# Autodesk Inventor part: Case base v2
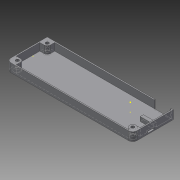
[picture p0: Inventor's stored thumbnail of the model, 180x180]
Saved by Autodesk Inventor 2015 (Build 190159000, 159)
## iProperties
Created: 2018-08
Part Number: Case base v2
Material: Generic
Document SubType Name: Modeling
Designer: Toby
Density: 1 g/cm^3
Appearance: Default
Author: Toby
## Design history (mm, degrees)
sketch "Sketch1"
  geometry: L1 (-84.862, 14.269)-(26.138, 14.269); L2 (26.138, 14.269)-(26.138, -23.731); L3 (26.138, -23.731)-(-84.862, -23.731); L4 (-84.862, -23.731)-(-84.862, 14.269); 1 further point
  constraints: 8 end point, 2 parallel, 1 horizontal, 1 perpendicular
  dimensions: "d0" = 38 distance between parallel lines of L3 L1; "d1" = 111 distance of L1.start L1.end
extrude "Extrusion1" new body sketch "Sketch1" distance "d2" = 1; taper "d3" = 0 deg
sketch "Sketch2"
  geometry: L1 (-84.862, 14.269)-(26.138, 14.269); L2 (26.138, 14.269)-(26.138, -23.731); L3 (26.138, -23.731)-(-84.862, -23.731); L4 (-84.862, -23.731)-(-84.862, 14.269); L5 (-83.862, 13.269)-(25.138, 13.269); L6 (25.138, 13.269)-(25.138, -22.731); L7 (25.138, -22.731)-(-83.862, -22.731); L8 (-83.862, -22.731)-(-83.862, 13.269); 1 further point
  constraints: 16 end point, 4 parallel, 2 horizontal, 2 perpendicular
  dimensions: "d4" = 1 distance between parallel lines of L5 L1; "d5" = 1 distance between parallel lines of L3 L7; "d6" = 1 distance between parallel lines of L4 L8; "d7" = 1 distance between parallel lines of L2 L6
extrude "Extrusion2" join sketch "Sketch2" distance "d8" = 7; taper "d9" = 0 deg
sketch "Sketch3"
  geometry: L1 (25.138, -22.731)-(25.138, 13.269) reference; L2 (25.138, -22.731)-(-83.862, -22.731) reference; C1 r 3 at (21.138, -18.731); 1 further point
  constraints: 1 centre point
  dimensions: "d10" = 6 diameter of C1; "d11" = 4 distance from line of L1 C1.centre; "d12" = 4 distance from line of L2 C1.centre
extrude "Extrusion3" join sketch "Sketch3" distance "d13" = 7; taper "d14" = 0 deg
sketch "Sketch4"
  geometry: C1 r 3 at (0, 0) reference; 2 further points
  constraints: 1 coincident
hole "Hole1" sketch "Sketch4" at (0, 0) diameter "d15" = 3; stored, may be unused: countersink angle "d19" = 90 deg, drill point angle "d21" = 118 deg; dims "d16" = 6, "d17" = 4, "d18" = 2, "d20" = 6
sketch "Sketch5"
  geometry: L1 (4, -4)-(0, -4); L2 (0, -4)-(0, -1.5); L3 (0, -1.5)-(4, -1.5); L4 (4, -1.5)-(4, -4); L5 (4, 32)-(4, -4) reference; L6 (4, 3)-(1.5, 3); L7 (1.5, 3)-(1.5, -1.5); L8 (1.5, -1.5)-(4, -1.5); L9 (4, -1.5)-(4, 3); 2 further points
  constraints: 16 end point, 4 parallel, 2 horizontal, 2 perpendicular, 2 point on line, 1 vertical alignment, 1 other
extrude "Extrusion4" join sketch "Sketch5" distance "d22" = 7; taper "d23" = 0 deg
sketch "Sketch6"
  geometry: L1 (25.138, 13.269)-(25.138, -15.731) reference; L2 (25.138, -0.731)-(13.138, -0.731); L3 (13.138, -0.731)-(13.138, -3.731); L4 (13.138, -3.731)-(25.138, -3.731); L5 (25.138, -3.731)-(25.138, -0.731); L6 (-83.862, 13.269)-(25.138, 13.269) reference; 1 further point
  constraints: 8 end point, 2 parallel, 1 horizontal, 1 perpendicular, 1 point on line
  dimensions: "d24" = 3 distance between parallel lines of L4 L2; "d25" = 14 distance between parallel lines of L6 L2; "d26" = 12 distance between parallel lines of L1 L3
extrude "Extrusion5" join sketch "Sketch6" distance "d27" = 4; taper "d28" = 0 deg
sketch "Sketch7"
  geometry: L1 (111, 0)-(0, 0) reference; L2 (0, -8)-(111, -8) reference; L3 (109, 0)-(94, 0); L4 (94, 0)-(94, -8); L5 (94, -8)-(109, -8); L6 (109, -8)-(109, 0); L7 (110, -1)-(110, -5) reference; 1 further point
  constraints: 8 end point, 2 parallel, 2 point on line, 1 horizontal, 1 perpendicular
  dimensions: "d29" = 1 distance between parallel lines of L7 L6; "d30" = 15 distance between parallel lines of L4 L6
extrude "Extrusion6" cut sketch "Sketch7" distance "d31" = 1; taper "d32" = 0 deg
sketch "Sketch8"
  geometry: 1 further point
sketch "Sketch9"
  geometry: L1 (-5, 20)-(-1, 20) reference; L2 (-1, 8)-(-1, 20) reference; L3 (-2.5, 20)-(-1, 20); L4 (-1, 20)-(-1, 14); L5 (-1, 14)-(-2.5, 14); L6 (-2.5, 14)-(-2.5, 20); 1 further point
  constraints: 8 end point, 2 parallel, 1 horizontal, 1 midpoint, 1 perpendicular, 1 point on line
  dimensions: "d33" = 6 distance of L5.end L3.start; "d34" = 1.5 distance between parallel lines of L2 L6
extrude "Extrusion7" cut sketch "Sketch9" distance "d35" = 1; taper "d36" = 0 deg
sketch "Sketch10"
  geometry: L1 (-84.862, 14.269)-(-89.862, 14.269); L2 (-89.862, 14.269)-(-89.862, -23.731); L3 (-89.862, -23.731)-(-84.862, -23.731); L4 (-84.862, -23.731)-(-84.862, 14.269); L5 (-84.862, -23.731)-(26.138, -23.731) reference; 1 further point
  constraints: 8 end point, 2 parallel, 1 collinear, 1 horizontal, 1 perpendicular
  dimensions: "d37" = 5 distance of L3.end L2.end
extrude "Extrusion8" join sketch "Sketch10" distance "d38" = 1; taper "d39" = 0 deg
sketch "Sketch11"
  geometry: L1 (-83.862, 13.269)-(-83.862, -22.731) reference; L2 (-89.862, 14.269)-(-83.862, 14.269); L3 (-83.862, 14.269)-(-83.862, 8.269); L4 (-83.862, 8.269)-(-89.862, 8.269); L5 (-89.862, 8.269)-(-89.862, 14.269); L6 (-89.862, -23.731)-(-83.862, -23.731); L7 (-83.862, -23.731)-(-83.862, -17.731); L8 (-83.862, -17.731)-(-89.862, -17.731); L9 (-89.862, -17.731)-(-89.862, -23.731); L10 (-89.862, 8.269)-(-88.862, 8.269); L11 (-88.862, 8.269)-(-88.862, -17.731); L12 (-88.862, -17.731)-(-89.862, -17.731); L13 (-89.862, -17.731)-(-89.862, 8.269); 1 further point
  constraints: 24 end point, 6 parallel, 3 horizontal, 3 perpendicular, 3 point on line
  dimensions: "d40" = 6 distance of L2.end L3.end; "d41" = 6 distance of L7.end L6.end; "d42" = 1 distance between parallel lines of L13 L11
extrude "Extrusion9" join sketch "Sketch11" distance "d43" = 7; taper "d44" = 0 deg
sketch "Sketch12"
  geometry: L1 (-84.862, 8.269)-(-83.862, 8.269); L2 (-83.862, 8.269)-(-83.862, -17.731); L3 (-83.862, -17.731)-(-84.862, -17.731); L4 (-84.862, -17.731)-(-84.862, 8.269); L5 (-84.862, -17.731)-(-88.862, -17.731) reference; L6 (-83.862, -22.731)-(-83.862, 13.269) reference; 1 further point
  constraints: 8 end point, 2 collinear, 2 parallel, 1 horizontal, 1 perpendicular
extrude "Extrusion10" cut sketch "Sketch12" distance "d45" = 7; taper "d46" = 0 deg
sketch "Sketch13"
  geometry: L1 (-88.862, 8.269)-(-83.862, 8.269) reference; L2 (-83.862, 8.269)-(-83.862, 13.269) reference; L3 (-83.862, -17.731)-(-88.862, -17.731) reference; 3 further points
  dimensions: "d47" = 3 distance from line of L1 point (-86.862, 11.269); "d48" = 3 distance from line of L2 point (-86.862, 11.269); "d49" = 3 distance from line of L3 point (-86.862, -20.731)
hole "Hole2" sketch "Sketch13" at (-86.862, 11.269), (-86.862, -20.731) diameter "d50" = 3; stored, may be unused: countersink angle "d54" = 90 deg, drill point angle "d56" = 118 deg; dims "d51" = 6, "d52" = 4, "d53" = 2, "d55" = 6
fillet "Fillet1" dims "d57" = 4
fillet "Fillet2" dims "d58" = 2
sketch "Sketch15"
  geometry: L1 (-85.862, -23.731)-(22.138, -23.731) reference; L2 (-89.862, 14.269)-(-83.862, 14.269); L3 (-83.862, 14.269)-(-83.862, -23.731); L4 (-83.862, -23.731)-(-89.862, -23.731); L5 (-89.862, -23.731)-(-89.862, 14.269); L6 (-83.862, 10.269)-(-83.862, 13.269) reference; 1 further point
  constraints: 8 end point, 2 parallel, 1 collinear, 1 horizontal, 1 perpendicular, 1 point on line
extrude "Extrusion11" cut sketch "Sketch15" distance "d59" = 10; taper "d60" = 0 deg
sketch "Sketch16"
  geometry: L1 (-83.862, 14.269)-(-91.862, 14.269); L2 (-91.862, 14.269)-(-91.862, -23.731); L3 (-91.862, -23.731)-(-83.862, -23.731); L4 (-83.862, -23.731)-(-83.862, 14.269); L5 (-83.862, -23.731)-(22.138, -23.731) reference; 1 further point
  constraints: 8 end point, 2 parallel, 1 collinear, 1 horizontal, 1 perpendicular
  dimensions: "d61" = 8 distance between parallel lines of L4 L2
extrude "Extrusion12" join sketch "Sketch16" distance "d62" = 1; taper "d63" = 0 deg
sketch "Sketch17"
  geometry: L1 (22.138, -23.731)-(-91.862, -23.731) reference; L2 (-91.862, 14.269)-(-90.862, 14.269); L3 (-90.862, 14.269)-(-90.862, -23.731); L4 (-90.862, -23.731)-(-91.862, -23.731); L5 (-91.862, -23.731)-(-91.862, 14.269); L6 (-90.862, 14.269)-(-83.862, 14.269); L7 (-83.862, 14.269)-(-83.862, 13.269); L8 (-83.862, 13.269)-(-90.862, 13.269); L9 (-90.862, 13.269)-(-90.862, 14.269); L10 (-83.862, -22.731)-(-90.862, -22.731); L11 (-90.862, -22.731)-(-90.862, -23.731); L12 (-90.862, -23.731)-(-83.862, -23.731); L13 (-83.862, -23.731)-(-83.862, -22.731); 1 further point
  constraints: 24 end point, 6 parallel, 3 horizontal, 3 perpendicular, 1 point on line
  dimensions: "d64" = 1 distance of L3.end L4.end
extrude "Extrusion13" join sketch "Sketch17" distance "d65" = 7; taper "d66" = 0 deg
sketch "Sketch18"
  geometry: 1 further point
sketch "Sketch19"
  geometry: 1 further point
sketch "Sketch20" dims "d67" = 6
  geometry: L1 (-91.862, 14.269)-(-91.862, -23.731) reference; L2 (9.138, 14.269)-(-91.862, 14.269) reference; L3 (-91.862, -23.731)-(22.138, -23.731) reference; L4 (-90.862, 13.269)-(-90.862, -22.731) reference; L5 (21.138, -22.731)-(-90.862, -22.731) reference; L6 (-90.862, -15.731)-(-86.862, -15.731); L7 (-86.862, -15.731)-(-86.862, -22.731); L8 (-86.862, -22.731)-(-90.862, -22.731); L9 (-90.862, -22.731)-(-90.862, -15.731); L10 (-86.862, -18.731)-(-83.862, -18.731); L11 (-83.862, -18.731)-(-83.862, -22.731); L12 (-83.862, -22.731)-(-86.862, -22.731); L13 (-86.862, -22.731)-(-86.862, -18.731); L14 (-86.862, 9.269)-(-83.862, 9.269); L15 (-83.862, 9.269)-(-83.862, 13.269); L16 (-83.862, 13.269)-(-86.862, 13.269); L17 (-86.862, 13.269)-(-86.862, 9.269); L18 (-90.862, 13.269)-(-86.862, 13.269); L19 (-86.862, 13.269)-(-86.862, 6.269); L20 (-86.862, 6.269)-(-90.862, 6.269); L21 (-90.862, 6.269)-(-90.862, 13.269); C1 r 3 at (-86.862, -18.731); 1 further point
  constraints: 32 end point, 8 parallel, 4 horizontal, 4 perpendicular, 4 point on line, 1 centre point, 1 vertical alignment, 2 other
  dimensions: "d68" = 5 distance from line of L1 L14.start; "d69" = 5 distance from line of L2 L14.start; "d70" = 6 diameter of C1; "d71" = 5 distance from line of L1 L10.start; "d72" = 5 distance from line of L3 L10.start
extrude "Extrusion14" join sketch "Sketch20" distance "d73" = 7; taper "d74" = 0 deg
sketch "Sketch21"
  geometry: L1 (-91.862, 14.269)-(9.138, 14.269) reference; L2 (-91.862, -23.731)-(-91.862, 14.269) reference; L3 (-91.862, -23.731)-(22.138, -23.731) reference; 3 further points
  dimensions: "d75" = 5 distance from line of L1 point (-86.862, 9.269); "d76" = 5 distance from line of L2 point (-86.862, 9.269); "d77" = 5 distance from line of L2 point (-86.862, -18.731); "d78" = 5 distance from line of L3 point (-86.862, -18.731)
hole "Hole3" sketch "Sketch21" at (-86.862, 9.269), (-86.862, -18.731) diameter "d79" = 3; stored, may be unused: countersink angle "d83" = 90 deg, drill point angle "d85" = 118 deg; dims "d80" = 6, "d81" = 4, "d82" = 2, "d84" = 6
fillet "Fillet3" dims "d86" = 4
sketch "Sketch22"
  geometry: C1 r 1.5 at (86.862, -18.731) reference; C2 r 1.5 at (86.862, 9.269) reference; C3 r 1.5 at (-21.138, -18.731) reference; 4 further points
  constraints: 3 coincident
hole "Hole4" sketch "Sketch22" at (86.862, -18.731), (86.862, 9.269), (-21.138, -18.731) diameter "d87" = 3; stored, may be unused: countersink angle "d91" = 90 deg, drill point angle "d93" = 118 deg; dims "d88" = 6, "d89" = 6, "d90" = 2, "d92" = 8
body "Solid1"
